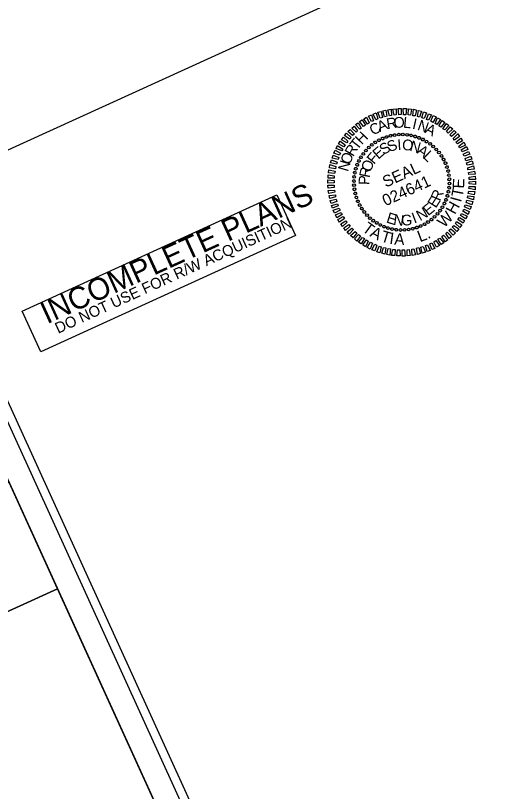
# Model space of a CAD drawing. Extents: x 2246788 to 2250969, y 662010 to 664598.
# Drawn here: x 2248379.4 to 2248628.8, y 663378.3 to 663785.8 of the extents above; entities that cross this region are included whole.
import ezdxf

# ---------------------------------------------------------------- set-up
doc = ezdxf.new("R2010")
doc.units = 0
for name, color, linetype in [('Sheet Layout Plan Border', 7, 'Continuous'), ('Sheet Plan CELL', 7, 'Continuous'), ('Sheet Plan Layout CELL', 7, 'Continuous'), ('Sheet Plot Border Inside CELL', 7, 'Continuous'), ('Sheet Plot Border Outside CELL', 7, 'Continuous'), ('Sheet Professional Seal CELL', 7, 'Continuous'), ('Sheet Sticker Incomplete CELL', 7, 'Continuous')]:
    doc.layers.add(name, color=color, linetype=linetype)

msp = doc.modelspace()

# ---------------------------------------------------------------- linework, layer by layer
at = {"layer": 'Sheet Layout Plan Border'}
msp.add_lwpolyline([(2248198.13, 663481.51), (2248575.77, 662652.77), (2249849.75, 663233.3), (2249502.05, 663996.33), (2249329.83, 663917.85), (2249242.13, 664110.3), (2248140.38, 663608.25)], close=True, dxfattribs=at)
at = {"layer": 'Sheet Plan CELL'}
for points in [[(2248313.69, 663677.29), (2246948.69, 663055.28), (2247384.08, 662099.81), (2248749.06, 662721.8)], [(2247384.08, 662099.81), (2246948.68, 663055.25), (2248131.62, 663594.34), (2248193.86, 663457.79), (2248375.89, 663540.73), (2248749.06, 662721.8)]]:
    msp.add_lwpolyline(points, close=True, dxfattribs=at)
at = {"layer": 'Sheet Plan Layout CELL'}
for points in [[(2248183.64, 663385.62), (2248401.37, 663484.84), (2248313.7, 663677.29), (2248095.94, 663578.07)], [(2246948.68, 663055.25), (2247384.08, 662099.81), (2248749.05, 662721.8), (2248401.35, 663484.83), (2248183.64, 663385.62), (2248095.94, 663578.07)]]:
    msp.add_lwpolyline(points, close=True, dxfattribs=at)
at = {"layer": 'Sheet Plot Border Inside CELL'}
msp.add_lwpolyline([(2247245.45, 662033.88), (2248761.46, 662724.71), (2248324.01, 663684.73), (2246807.99, 662993.9)], close=True, dxfattribs=at)
at = {"layer": 'Sheet Plot Border Outside CELL'}
msp.add_lwpolyline([(2247241.92, 662010.29), (2248773.86, 662708.37), (2248319.81, 663704.79), (2246787.87, 663006.71)], close=True, dxfattribs=at)
at = {"layer": 'Sheet Professional Seal CELL'}
for p, q in [((2248576.34, 663722.65), (2248576.34, 663722.65)), ((2248578.44, 663723.11), (2248578.44, 663723.11)), ((2248580.64, 663723.34), (2248580.64, 663723.34)), ((2248582.83, 663723.35), (2248582.83, 663723.35)), ((2248585.02, 663723.25), (2248585.02, 663723.25)), ((2248587.17, 663722.86), (2248587.17, 663722.86)), ((2248589.33, 663722.36), (2248589.33, 663722.36)), ((2248568.36, 663719.17), (2248568.36, 663719.17)), ((2248570.19, 663720.34), (2248570.19, 663720.34)), ((2248572.17, 663721.3), (2248572.17, 663721.3)), ((2248574.24, 663722.07), (2248574.24, 663722.07)), ((2248591.36, 663721.64), (2248591.36, 663721.64)), ((2248593.41, 663720.76), (2248593.41, 663720.76)), ((2248595.27, 663719.68), (2248595.27, 663719.68)), ((2248597.11, 663718.43), (2248597.11, 663718.43)), ((2248563.37, 663714.92), (2248563.37, 663714.92)), ((2248564.86, 663716.48), (2248564.86, 663716.48)), ((2248566.52, 663717.9), (2248566.52, 663717.9)), ((2248598.83, 663717.07), (2248598.83, 663717.07)), ((2248600.38, 663715.59), (2248600.38, 663715.59)), ((2248560.76, 663711.37), (2248560.76, 663711.37)), ((2248562.01, 663713.2), (2248562.01, 663713.2)), ((2248601.8, 663713.92), (2248601.8, 663713.92)), ((2248603.08, 663712.09), (2248603.08, 663712.09)), ((2248604.24, 663710.26), (2248604.24, 663710.26)), ((2248558.81, 663707.45), (2248558.81, 663707.45)), ((2248559.69, 663709.5), (2248559.69, 663709.5)), ((2248605.2, 663708.28), (2248605.2, 663708.28)), ((2248605.98, 663706.21), (2248605.98, 663706.21)), ((2248557.59, 663703.27), (2248557.59, 663703.27)), ((2248558.09, 663705.42), (2248558.09, 663705.42)), ((2248606.55, 663704.11), (2248606.55, 663704.11)), ((2248607.01, 663702.01), (2248607.01, 663702.01)), ((2248557.1, 663698.92), (2248557.1, 663698.92)), ((2248557.2, 663701.11), (2248557.2, 663701.11)), ((2248582.18, 663698.27), (2248582.18, 663698.27)), ((2248607.25, 663699.81), (2248607.25, 663699.81)), ((2248557.11, 663696.73), (2248557.11, 663696.73)), ((2248557.34, 663694.53), (2248557.34, 663694.53)), ((2248607.16, 663695.43), (2248607.16, 663695.43)), ((2248607.26, 663697.62), (2248607.26, 663697.62)), ((2248557.8, 663692.43), (2248557.8, 663692.43)), ((2248558.38, 663690.33), (2248558.38, 663690.33)), ((2248606.26, 663691.12), (2248606.26, 663691.12)), ((2248606.77, 663693.27), (2248606.77, 663693.27)), ((2248559.15, 663688.27), (2248559.15, 663688.27)), ((2248560.11, 663686.29), (2248560.11, 663686.29)), ((2248604.66, 663687.04), (2248604.66, 663687.04)), ((2248605.54, 663689.09), (2248605.54, 663689.09)), ((2248561.28, 663684.45), (2248561.28, 663684.45)), ((2248562.55, 663682.62), (2248562.55, 663682.62)), ((2248600.98, 663681.62), (2248600.98, 663681.62)), ((2248602.34, 663683.34), (2248602.34, 663683.34)), ((2248603.59, 663685.17), (2248603.59, 663685.17)), ((2248563.97, 663680.96), (2248563.97, 663680.96)), ((2248565.53, 663679.47), (2248565.53, 663679.47)), ((2248567.25, 663678.11), (2248567.25, 663678.11)), ((2248595.99, 663677.37), (2248595.99, 663677.37)), ((2248597.83, 663678.65), (2248597.83, 663678.65)), ((2248599.49, 663680.06), (2248599.49, 663680.06)), ((2248569.08, 663676.86), (2248569.08, 663676.86)), ((2248570.94, 663675.78), (2248570.94, 663675.78)), ((2248572.99, 663674.9), (2248572.99, 663674.9)), ((2248575.03, 663674.18), (2248575.03, 663674.18)), ((2248577.18, 663673.68), (2248577.18, 663673.68)), ((2248579.33, 663673.29), (2248579.33, 663673.29)), ((2248585.92, 663673.43), (2248585.92, 663673.43)), ((2248588.02, 663673.9), (2248588.02, 663673.9)), ((2248590.12, 663674.47), (2248590.12, 663674.47)), ((2248592.18, 663675.25), (2248592.18, 663675.25)), ((2248594.16, 663676.2), (2248594.16, 663676.2)), ((2248581.52, 663673.19), (2248581.52, 663673.19)), ((2248583.72, 663673.2), (2248583.72, 663673.2))]:
    msp.add_line(p, q, dxfattribs=at)
for points in [[(2248568.54, 663731.07), (2248567.19, 663734.03), (2248568.71, 663734.67), (2248569.65, 663731.52)], [(2248570.88, 663731.97), (2248569.71, 663735.01), (2248571.34, 663735.42), (2248572.05, 663732.29)], [(2248573.23, 663732.6), (2248572.31, 663735.7), (2248573.91, 663736.16), (2248574.38, 663732.96)], [(2248575.77, 663733.16), (2248574.88, 663736.32), (2248576.59, 663736.67), (2248576.83, 663733.37)], [(2248578.23, 663733.56), (2248577.62, 663736.7), (2248579.24, 663736.88), (2248579.33, 663733.68)], [(2248580.65, 663733.68), (2248580.39, 663737.02), (2248581.91, 663737.06), (2248581.84, 663733.84)], [(2248583.09, 663733.75), (2248583, 663736.95), (2248584.7, 663736.96), (2248584.32, 663733.7)], [(2248585.66, 663733.66), (2248585.71, 663736.81), (2248587.42, 663736.66), (2248586.77, 663733.5)], [(2248587.99, 663733.24), (2248588.38, 663736.6), (2248590, 663736.18), (2248589.24, 663733.15)], [(2248590.48, 663732.72), (2248591.02, 663735.99), (2248592.66, 663735.53), (2248591.64, 663732.48)], [(2248592.85, 663732.1), (2248593.64, 663735.32), (2248595.23, 663734.72), (2248594.03, 663731.81)], [(2248562.11, 663727.59), (2248560.05, 663730.17), (2248561.49, 663730.99), (2248563.13, 663728.22)], [(2248564.16, 663728.85), (2248562.34, 663731.54), (2248563.8, 663732.43), (2248565.19, 663729.49)], [(2248566.34, 663730.12), (2248564.76, 663732.97), (2248566.28, 663733.61), (2248567.45, 663730.57)], [(2248595.22, 663731.25), (2248596.2, 663734.28), (2248597.79, 663733.69), (2248596.23, 663730.84)], [(2248597.56, 663730.34), (2248598.72, 663733.34), (2248600.23, 663732.55), (2248598.61, 663729.72)], [(2248599.73, 663729.19), (2248601.09, 663732.12), (2248602.55, 663731.19), (2248600.67, 663728.58)], [(2248601.76, 663727.86), (2248603.39, 663730.69), (2248604.87, 663729.72), (2248602.82, 663727.25)], [(2248558.24, 663724.5), (2248555.94, 663726.75), (2248557.17, 663727.81), (2248559.05, 663725.26)], [(2248560.15, 663726.09), (2248557.89, 663728.52), (2248559.29, 663729.54), (2248561, 663726.75)], [(2248603.86, 663726.4), (2248605.68, 663729.16), (2248606.92, 663728.02), (2248604.8, 663725.79)], [(2248605.66, 663724.86), (2248607.72, 663727.45), (2248608.98, 663726.26), (2248606.57, 663724.07)], [(2248554.77, 663720.89), (2248552.15, 663722.77), (2248553.27, 663724.05), (2248555.59, 663721.76)], [(2248556.34, 663722.76), (2248553.95, 663724.86), (2248555.07, 663726.03), (2248557.35, 663723.55)], [(2248607.46, 663723.1), (2248609.69, 663725.54), (2248610.83, 663724.36), (2248608.35, 663722.35)], [(2248609.18, 663721.24), (2248611.61, 663723.62), (2248612.57, 663722.24), (2248609.93, 663720.43)], [(2248551.83, 663716.86), (2248549.09, 663718.41), (2248549.88, 663719.81), (2248552.58, 663717.86)], [(2248553.31, 663718.91), (2248550.51, 663720.6), (2248551.59, 663721.97), (2248553.93, 663719.85)], [(2248610.72, 663719.31), (2248613.19, 663721.48), (2248614.17, 663720.06), (2248611.43, 663718.48)], [(2248612.13, 663717.31), (2248614.79, 663719.3), (2248615.63, 663717.81), (2248612.81, 663716.3)], [(2248549.55, 663712.46), (2248546.63, 663713.55), (2248547.23, 663715.14), (2248550.12, 663713.49)], [(2248550.72, 663714.7), (2248547.77, 663715.99), (2248548.57, 663717.51), (2248551.32, 663715.69)], [(2248613.39, 663715.25), (2248616.19, 663716.97), (2248616.98, 663715.46), (2248613.98, 663714.2)], [(2248614.48, 663713), (2248617.37, 663714.48), (2248618.08, 663712.94), (2248614.97, 663711.91)], [(2248547.97, 663707.73), (2248544.79, 663708.43), (2248545.26, 663710.07), (2248548.23, 663708.84)], [(2248548.77, 663710.19), (2248545.6, 663710.99), (2248546.26, 663712.56), (2248549.17, 663711.25)], [(2248615.47, 663710.7), (2248618.47, 663711.96), (2248619.06, 663710.42), (2248615.88, 663709.57)], [(2248547.39, 663705.38), (2248544.23, 663705.81), (2248544.49, 663707.52), (2248547.59, 663706.51)], [(2248616.24, 663708.42), (2248619.27, 663709.47), (2248619.8, 663707.84), (2248616.51, 663707.22)], [(2248616.93, 663705.93), (2248619.92, 663706.85), (2248620.3, 663705.16), (2248617, 663704.81)], [(2248546.66, 663700.48), (2248543.55, 663700.44), (2248543.58, 663702.16), (2248546.81, 663701.6)], [(2248546.86, 663702.94), (2248543.69, 663703.14), (2248544.02, 663704.83), (2248547.21, 663704.09)], [(2248617.34, 663703.48), (2248620.43, 663704.17), (2248620.79, 663702.53), (2248617.41, 663702.36)], [(2248546.7, 663697.98), (2248543.4, 663697.74), (2248543.44, 663699.46), (2248546.7, 663699.18)], [(2248617.65, 663700.98), (2248620.84, 663701.45), (2248620.89, 663699.77), (2248617.58, 663699.8)], [(2248617.65, 663698.57), (2248620.95, 663698.81), (2248620.91, 663697.08), (2248617.65, 663697.36)], [(2248546.7, 663695.56), (2248543.51, 663695.09), (2248543.46, 663696.77), (2248546.77, 663696.74)], [(2248547.02, 663693.06), (2248543.93, 663692.37), (2248543.56, 663694.02), (2248546.95, 663694.19)], [(2248617.7, 663696.06), (2248620.81, 663696.1), (2248620.77, 663694.38), (2248617.54, 663694.94)], [(2248547.42, 663690.61), (2248544.44, 663689.69), (2248544.05, 663691.38), (2248547.35, 663691.73)], [(2248616.96, 663691.16), (2248620.12, 663690.74), (2248619.86, 663689.02), (2248616.76, 663690.03)], [(2248617.5, 663693.6), (2248620.67, 663693.4), (2248620.34, 663691.71), (2248617.14, 663692.45)], [(2248548.12, 663688.13), (2248545.08, 663687.07), (2248544.56, 663688.7), (2248547.85, 663689.32)], [(2248548.88, 663685.84), (2248545.89, 663684.58), (2248545.29, 663686.12), (2248548.48, 663686.97)], [(2248615.58, 663686.36), (2248618.75, 663685.55), (2248618.09, 663683.98), (2248615.18, 663685.3)], [(2248616.38, 663688.81), (2248619.56, 663688.12), (2248619.1, 663686.48), (2248616.12, 663687.7)], [(2248549.88, 663683.54), (2248546.98, 663682.06), (2248546.28, 663683.6), (2248549.38, 663684.63)], [(2248550.96, 663681.29), (2248548.17, 663679.58), (2248547.37, 663681.08), (2248550.37, 663682.34)], [(2248613.63, 663681.84), (2248616.58, 663680.55), (2248615.79, 663679.03), (2248613.03, 663680.85)], [(2248614.81, 663684.08), (2248617.72, 663682.99), (2248617.13, 663681.4), (2248614.23, 663683.05)], [(2248552.23, 663679.23), (2248549.56, 663677.24), (2248548.72, 663678.73), (2248551.55, 663680.24)], [(2248553.63, 663677.23), (2248551.16, 663675.06), (2248550.18, 663676.48), (2248552.92, 663678.06)], [(2248611.04, 663677.64), (2248613.84, 663675.95), (2248612.76, 663674.58), (2248610.42, 663676.7)], [(2248612.52, 663679.69), (2248615.26, 663678.13), (2248614.47, 663676.73), (2248611.77, 663678.68)], [(2248555.17, 663675.3), (2248552.74, 663672.92), (2248551.78, 663674.3), (2248554.42, 663676.11)], [(2248556.9, 663673.45), (2248554.66, 663671), (2248553.52, 663672.18), (2248556.01, 663674.19)], [(2248608.01, 663673.78), (2248610.4, 663671.68), (2248609.28, 663670.52), (2248607, 663672.99)], [(2248609.58, 663675.65), (2248612.2, 663673.77), (2248611.08, 663672.49), (2248608.77, 663674.79)], [(2248558.69, 663671.68), (2248556.63, 663669.09), (2248555.37, 663670.28), (2248557.78, 663672.47)], [(2248560.49, 663670.14), (2248558.67, 663667.39), (2248557.44, 663668.53), (2248559.55, 663670.76)], [(2248562.59, 663668.68), (2248560.97, 663665.85), (2248559.48, 663666.82), (2248561.54, 663669.3)], [(2248604.2, 663670.45), (2248606.47, 663668.02), (2248605.06, 663667), (2248603.35, 663669.79)], [(2248606.12, 663672.04), (2248608.41, 663669.79), (2248607.18, 663668.73), (2248605.31, 663671.29)], [(2248564.62, 663667.35), (2248563.26, 663664.42), (2248561.8, 663665.35), (2248563.68, 663667.97)], [(2248566.8, 663666.2), (2248565.64, 663663.2), (2248564.12, 663663.99), (2248565.74, 663666.82)], [(2248569.14, 663665.29), (2248568.15, 663662.26), (2248566.56, 663662.85), (2248568.12, 663665.7)], [(2248595.81, 663665.47), (2248597.16, 663662.52), (2248595.64, 663661.88), (2248594.7, 663665.02)], [(2248598.02, 663666.42), (2248599.59, 663663.57), (2248598.07, 663662.93), (2248596.9, 663665.97)], [(2248600.19, 663667.69), (2248602.02, 663665), (2248600.55, 663664.12), (2248599.16, 663667.05)], [(2248602.25, 663668.96), (2248604.3, 663666.38), (2248602.86, 663665.56), (2248601.22, 663668.32)], [(2248571.5, 663664.44), (2248570.71, 663661.23), (2248569.12, 663661.82), (2248570.32, 663664.73)], [(2248573.87, 663663.82), (2248573.33, 663660.55), (2248571.69, 663661.01), (2248572.72, 663664.06)], [(2248576.36, 663663.31), (2248575.97, 663659.94), (2248574.35, 663660.36), (2248575.11, 663663.4)], [(2248578.69, 663662.89), (2248578.65, 663659.73), (2248576.93, 663659.88), (2248577.58, 663663.04)], [(2248581.26, 663662.79), (2248581.35, 663659.59), (2248579.65, 663659.59), (2248580.03, 663662.84)], [(2248583.7, 663662.86), (2248583.96, 663659.52), (2248582.44, 663659.49), (2248582.51, 663662.7)], [(2248586.12, 663662.98), (2248586.73, 663659.85), (2248585.11, 663659.66), (2248585.02, 663662.86)], [(2248588.58, 663663.38), (2248589.47, 663660.22), (2248587.76, 663659.88), (2248587.52, 663663.17)], [(2248591.13, 663663.94), (2248592.04, 663660.84), (2248590.44, 663660.38), (2248589.97, 663663.58)], [(2248593.48, 663664.57), (2248594.64, 663661.53), (2248593.02, 663661.12), (2248592.3, 663664.26)]]:
    msp.add_lwpolyline(points, close=True, dxfattribs=at)
for centre, major_axis in [((2248574.21, 663722.05), (-0.229, 0.683)), ((2248576.32, 663722.66), (-0.168, 0.7)), ((2248578.46, 663723.07), (-0.107, 0.712)), ((2248580.64, 663723.3), (-0.044, 0.719)), ((2248582.83, 663723.34), (0.019, 0.72)), ((2248585.01, 663723.19), (0.081, 0.715)), ((2248587.17, 663722.85), (0.143, 0.706)), ((2248589.29, 663722.32), (0.204, 0.69)), ((2248591.36, 663721.61), (0.264, 0.67)), ((2248566.56, 663717.9), (-0.448, 0.563)), ((2248568.33, 663719.18), (-0.398, 0.6)), ((2248570.2, 663720.31), (-0.344, 0.633)), ((2248572.17, 663721.27), (-0.287, 0.66)), ((2248593.36, 663720.72), (0.321, 0.644)), ((2248595.28, 663719.66), (0.376, 0.614)), ((2248597.09, 663718.43), (0.428, 0.579)), ((2248562.01, 663713.18), (-0.579, 0.428)), ((2248563.39, 663714.89), (-0.539, 0.477)), ((2248564.91, 663716.46), (-0.496, 0.522)), ((2248598.79, 663717.06), (0.477, 0.539)), ((2248600.37, 663715.54), (0.522, 0.496)), ((2248601.8, 663713.89), (0.563, 0.448)), ((2248559.73, 663709.46), (-0.644, 0.321)), ((2248560.79, 663711.37), (-0.614, 0.376)), ((2248603.09, 663712.12), (0.6, 0.398)), ((2248604.21, 663710.24), (0.633, 0.344)), ((2248558.13, 663705.39), (-0.69, 0.204)), ((2248558.84, 663707.46), (-0.67, 0.264)), ((2248605.17, 663708.28), (0.66, 0.287)), ((2248605.96, 663706.23), (0.683, 0.229)), ((2248557.26, 663701.1), (-0.715, 0.081)), ((2248557.6, 663703.27), (-0.706, 0.143)), ((2248606.56, 663704.13), (0.7, 0.168)), ((2248606.98, 663701.98), (0.712, 0.107)), ((2248557.1, 663698.92), (-0.72, 0.019)), ((2248607.21, 663699.81), (0.719, 0.044)), ((2248607.25, 663697.62), (0.72, -0.019)), ((2248557.14, 663696.73), (-0.719, -0.044)), ((2248557.37, 663694.56), (-0.712, -0.107)), ((2248606.75, 663693.28), (0.706, -0.143)), ((2248607.1, 663695.44), (0.715, -0.081)), ((2248557.79, 663692.41), (-0.7, -0.168)), ((2248558.39, 663690.31), (-0.683, -0.229)), ((2248605.51, 663689.08), (0.67, -0.264)), ((2248606.23, 663691.15), (0.69, -0.204)), ((2248559.18, 663688.27), (-0.66, -0.287)), ((2248560.14, 663686.3), (-0.633, -0.344)), ((2248603.56, 663685.17), (0.614, -0.376)), ((2248604.62, 663687.09), (0.644, -0.321)), ((2248561.27, 663684.42), (-0.6, -0.398)), ((2248562.55, 663682.65), (-0.563, -0.448)), ((2248563.99, 663681), (-0.522, -0.496)), ((2248600.96, 663681.66), (0.539, -0.477)), ((2248602.34, 663683.36), (0.579, -0.428)), ((2248565.56, 663679.48), (-0.477, -0.539)), ((2248567.26, 663678.11), (-0.428, -0.579)), ((2248569.08, 663676.88), (-0.376, -0.614)), ((2248596.02, 663677.36), (0.398, -0.6)), ((2248597.79, 663678.65), (0.448, -0.563)), ((2248599.44, 663680.08), (0.496, -0.522)), ((2248570.99, 663675.82), (-0.321, -0.644)), ((2248572.99, 663674.93), (-0.264, -0.67)), ((2248575.06, 663674.22), (-0.204, -0.69)), ((2248577.18, 663673.69), (-0.143, -0.706)), ((2248579.34, 663673.35), (-0.081, -0.715)), ((2248581.53, 663673.2), (-0.019, -0.72)), ((2248583.71, 663673.24), (0.044, -0.719)), ((2248585.89, 663673.47), (0.107, -0.712)), ((2248588.04, 663673.89), (0.168, -0.7)), ((2248590.14, 663674.49), (0.229, -0.683)), ((2248592.18, 663675.27), (0.287, -0.66)), ((2248594.15, 663676.23), (0.344, -0.633))]:
    msp.add_ellipse(centre, major_axis=major_axis, ratio=0.999708, dxfattribs=at)
at = {"layer": 'Sheet Sticker Incomplete CELL'}
msp.add_lwpolyline([(2248392.59, 663609.27), (2248382.85, 663630.66), (2248516.62, 663691.61), (2248526.36, 663670.23)], close=True, dxfattribs=at)

# ---------------------------------------------------------------- texts
at = {"layer": 'Sheet Professional Seal CELL'}
for s, height, rotation, p in [('A', 5.64, 23.5326, (2248570.74, 663724.55)), ('R', 5.64, 9.1334, (2248574.65, 663726.11)), ('O', 5.64, 1.9334, (2248578.01, 663726.81)), ('L', 5.64, 354.7331, (2248582.78, 663726.96)), ('I', 5.64, 347.5324, (2248587.46, 663726.45)), ('N', 5.64, 340.3312, (2248590.06, 663725.93)), ('C', 5.64, 30.7321, (2248567.28, 663722.63)), ('A', 5.64, 333.1294, (2248593.97, 663724.47)), ('H', 5.64, 45.1317, (2248561.19, 663717.66)), ('T', 5.64, 52.332, (2248558.92, 663714.81)), ('S', 5.64, 31.7679, (2248572.64, 663712.44)), ('S', 5.64, 22.4127, (2248575.89, 663713.98)), ('I', 5.64, 3.7019, (2248580.1, 663715.13)), ('O', 5.64, 354.3457, (2248582.21, 663715.32)), ('N', 5.64, 344.9889, (2248586.08, 663714.89)), ('R', 5.64, 59.5328, (2248556.74, 663711.4)), ('F', 5.64, 50.4793, (2248567.65, 663707.36)), ('E', 5.64, 41.1233, (2248569.93, 663710.05)), ('A', 5.64, 326.2725, (2248589.76, 663713.71)), ('L', 5.64, 316.9131, (2248592.96, 663711.38)), ('O', 5.64, 66.734, (2248554.88, 663707.15)), ('N', 5.64, 73.9358, (2248553.99, 663703.55)), ('R', 5.64, 78.5519, (2248565.29, 663700.35)), ('O', 5.64, 69.1935, (2248565.87, 663703.31)), ('SEAL', 5.998, 24.5123, (2248573.82, 663695.39)), ('P', 5.64, 87.9112, (2248565.16, 663696.78)), ('024641', 5.998, 24.5123, (2248573.7, 663685.6)), ('E', 6, 87.6312, (2248614.96, 663694.91)), ('R', 5.64, 66.9937, (2248602.37, 663687.97)), ('T', 6, 79.1093, (2248614.1, 663690.09)), ('E', 5.64, 57.6364, (2248600.11, 663684.36)), ('I', 6, 74.3449, (2248613.31, 663687.47)), ('E', 5.64, 38.924, (2248596.1, 663680.39)), ('H', 6, 61.8333, (2248610.23, 663680.98)), ('E', 5.64, 342.7892, (2248573.75, 663677.23)), ('N', 5.64, 352.1462, (2248577.6, 663676.02)), ('I', 5.64, 20.2135, (2248588.74, 663676.53)), ('N', 5.64, 29.5687, (2248591.85, 663677.79)), ('W', 6, 46.126, (2248604.5, 663674.03)), ('T', 6, 323.6774, (2248561.08, 663672.96)), ('G', 5.64, 1.5025, (2248581.99, 663675.54)), ('A', 6, 332.1992, (2248565.07, 663670.11)), ('T', 6, 343.2776, (2248570.8, 663667.35)), ('I', 6, 351.7994, (2248575.51, 663666)), ('A', 6, 356.5639, (2248578.21, 663665.56)), ('L', 6, 20.425, (2248591.78, 663666.75)), ('.', 6, 28.2883, (2248596, 663668.36))]:
    msp.add_text(s, height=height, rotation=rotation, dxfattribs=at).set_placement(p)
at = {"layer": 'Sheet Sticker Incomplete CELL'}
for s, height, p in [('INCOMPLETE PLANS', 11.52, (2248395.89, 663623.63)), ('DO NOT USE FOR R/W ACQUISITION', 5.76, (2248401.73, 663618.66))]:
    msp.add_text(s, height=height, rotation=24.4979, dxfattribs=at).set_placement(p)

doc.saveas('drawing.dxf')
